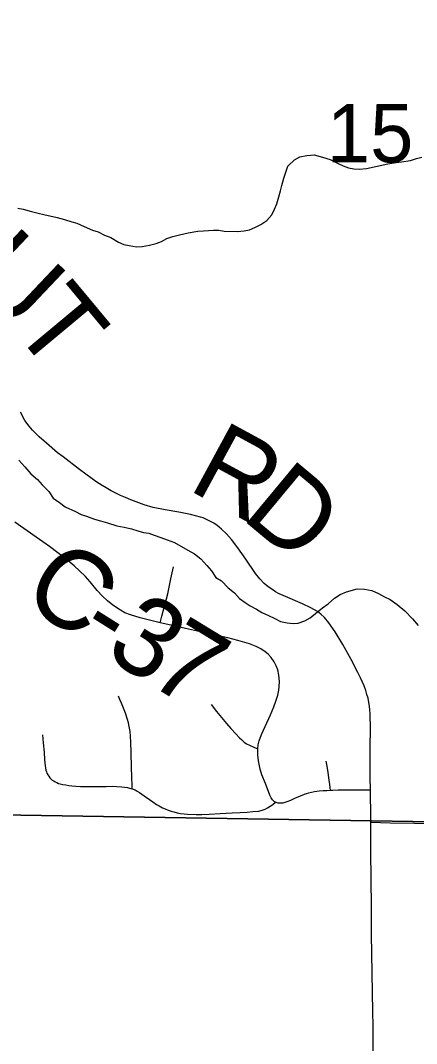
# Model space of a CAD drawing. Extents: x -8.8 to 41.4, y 0 to 34.6.
# Drawn here: x 2.586 to 2.87, y 15.426 to 16.161 of the extents above; entities that cross this region are included whole.
import ezdxf

# ---------------------------------------------------------------- set-up
doc = ezdxf.new("R2010")
doc.units = 0
for name, color, linetype in [('GM_X_Corporation', 7, 'Continuous'), ('GM_X_County_Road', 7, 'Continuous'), ('GM_X_Minor_River', 7, 'Continuous'), ('GM_X_Township_Road', 7, 'Continuous'), ('GM_X_Township_Road_Text', 7, 'Continuous'), ('GM_X_Township_Text', 7, 'Continuous')]:
    doc.layers.add(name, color=color, linetype=linetype)

msp = doc.modelspace()

# ---------------------------------------------------------------- linework, layer by layer
at = {"layer": 'GM_X_Corporation'}
for points in [[(2.35425, 16.60371), (3.32694, 16.59683), (3.3275, 15.57832), (2.34821, 15.59413)], [(2.34821, 15.59413), (3.3275, 15.57832), (3.32677, 14.56494), (2.34975, 14.59623)]]:
    msp.add_lwpolyline(points, close=True, dxfattribs=at)
at = {"layer": 'GM_X_County_Road'}
for points in [[(2.83763, 15.58529), (2.83742, 15.59449), (2.83723, 15.60243), (2.83721, 15.60834), (2.83716, 15.61761), (2.83712, 15.62667), (2.83714, 15.63601), (2.83725, 15.65583), (2.83716, 15.65981), (2.83696, 15.66326), (2.83679, 15.66619), (2.83652, 15.66869), (2.83605, 15.67147), (2.8355, 15.67452), (2.83476, 15.6772), (2.83383, 15.68007), (2.83263, 15.68322), (2.83142, 15.68599), (2.83003, 15.68905), (2.82818, 15.69299), (2.82339, 15.70232), (2.81735, 15.71309), (2.81182, 15.72202), (2.80722, 15.72856), (2.80414, 15.73233), (2.80152, 15.73485), (2.79915, 15.73667), (2.79442, 15.7394), (2.78827, 15.74223), (2.77457, 15.74818), (2.77172, 15.74947), (2.76895, 15.75098), (2.76623, 15.75267), (2.76368, 15.75449), (2.76073, 15.75687), (2.75758, 15.7602), (2.75458, 15.7641), (2.74756, 15.77443), (2.74191, 15.78254), (2.73743, 15.78841), (2.73377, 15.79255), (2.73024, 15.79592), (2.72843, 15.79743), (2.72693, 15.79859), (2.72452, 15.80016), (2.72228, 15.80149), (2.7203, 15.80246), (2.71844, 15.80328), (2.71688, 15.80395), (2.71504, 15.80463), (2.71142, 15.80556), (2.70792, 15.80646), (2.7031, 15.80737), (2.69944, 15.8081), (2.68962, 15.80972), (2.68104, 15.81147), (2.67441, 15.81337), (2.66504, 15.81694), (2.66098, 15.81868), (2.65759, 15.82019), (2.65404, 15.82183), (2.65086, 15.82349), (2.6472, 15.82551), (2.64436, 15.82726), (2.6404, 15.82977), (2.63707, 15.8321), (2.628, 15.83871), (2.61618, 15.84779), (2.61226, 15.85086), (2.60417, 15.85764), (2.599, 15.86216), (2.59408, 15.86696), (2.59169, 15.86989), (2.58875, 15.87394), (2.58551, 15.88004)], [(2.83924, 15.41958), (2.83909, 15.43879), (2.83895, 15.44935), (2.83806, 15.50465), (2.83791, 15.52579), (2.83783, 15.54318), (2.8375, 15.56555), (2.83763, 15.58529)]]:
    msp.add_lwpolyline(points, dxfattribs=at)
at = {"layer": 'GM_X_Minor_River'}
for points in [[(2.6561, 16.0022), (2.65984, 16.00055), (2.66361, 15.99965), (2.6689, 15.9987), (2.67309, 15.99893), (2.67844, 15.99988), (2.68305, 16.00124), (2.6869, 16.00262), (2.69078, 16.00476), (2.69501, 16.00613), (2.7, 16.00748), (2.70613, 16.00878), (2.71302, 16.01005), (2.71721, 16.01028), (2.72445, 16.01079), (2.72825, 16.01065), (2.73203, 16.01013), (2.74152, 16.00979), (2.74649, 16.01038), (2.75031, 16.011), (2.75417, 16.01277), (2.75843, 16.0149), (2.76272, 16.01778), (2.76628, 16.02184), (2.76833, 16.02595), (2.76999, 16.0297), (2.77131, 16.0346), (2.77261, 16.03911), (2.7735, 16.04288), (2.77484, 16.04816), (2.77653, 16.05305), (2.77781, 16.05681), (2.78253, 16.0612), (2.78641, 16.06335), (2.79138, 16.06431), (2.79673, 16.06488), (2.80274, 16.06314), (2.80838, 16.06142), (2.81398, 16.05855), (2.81773, 16.0569), (2.82148, 16.05562), (2.82525, 16.05473), (2.82943, 16.05458), (2.83439, 16.05516), (2.84971, 16.05842), (2.85583, 16.05934), (2.85965, 16.05996), (2.86615, 16.06087), (2.87038, 16.06224), (2.87421, 16.06324)], [(2.5836, 16.02648), (2.58739, 16.02596), (2.59341, 16.02423), (2.5983, 16.02291), (2.60245, 16.022), (2.61187, 16.01976), (2.61715, 16.01843), (2.62241, 16.01672), (2.62618, 16.01583), (2.63141, 16.01336), (2.6374, 16.01086), (2.64154, 16.00957), (2.64601, 16.00713), (2.65051, 16.00545), (2.6561, 16.0022)], [(2.58431, 15.84538), (2.5887, 15.84066), (2.59308, 15.83556), (2.59788, 15.83158), (2.60116, 15.82766), (2.60593, 15.82293), (2.60918, 15.81824), (2.61363, 15.81504), (2.61769, 15.81185), (2.62518, 15.80854), (2.62928, 15.80649), (2.63304, 15.80522), (2.63867, 15.80312), (2.64318, 15.80181), (2.64808, 15.80049), (2.65484, 15.79835), (2.66013, 15.7974), (2.6654, 15.79607), (2.66992, 15.79477), (2.67405, 15.79348), (2.67784, 15.79296), (2.68159, 15.79169), (2.68647, 15.78999), (2.69097, 15.78831), (2.69622, 15.78622), (2.70591, 15.78092), (2.71075, 15.77809), (2.71519, 15.77451), (2.71958, 15.76978), (2.72286, 15.76586), (2.72611, 15.76118), (2.7302, 15.75875), (2.73496, 15.75364), (2.73939, 15.75006), (2.74305, 15.74612), (2.74713, 15.74331), (2.75085, 15.7409), (2.75532, 15.73845), (2.75904, 15.73604), (2.7639, 15.73396), (2.76801, 15.73191)], [(2.76801, 15.73191), (2.77249, 15.72947), (2.77739, 15.72853), (2.78156, 15.728), (2.78537, 15.72825), (2.78999, 15.72998), (2.79387, 15.73213), (2.79779, 15.73541), (2.80287, 15.73941), (2.80678, 15.74231), (2.81149, 15.74633), (2.81538, 15.74885), (2.82002, 15.75097), (2.82769, 15.75298), (2.83301, 15.75279), (2.8383, 15.75184), (2.84316, 15.74976), (2.84726, 15.74733), (2.85136, 15.74528), (2.85656, 15.74167), (2.8621, 15.73729), (2.86759, 15.73139), (2.8716, 15.72668)]]:
    msp.add_lwpolyline(points, dxfattribs=at)
at = {"layer": 'GM_X_Township_Road'}
for points in [[(2.83721, 15.60834), (2.83541, 15.60833), (2.83031, 15.60836), (2.82391, 15.60835), (2.81755, 15.60835), (2.81392, 15.60825), (2.81008, 15.60814), (2.80862, 15.60807), (2.80589, 15.60797), (2.80321, 15.60781), (2.80036, 15.60753), (2.79699, 15.60713), (2.79479, 15.60678), (2.79265, 15.60628), (2.79104, 15.60581), (2.78958, 15.60532), (2.78661, 15.604), (2.7827, 15.60229), (2.77978, 15.601), (2.77705, 15.59994), (2.77566, 15.59949), (2.7742, 15.59913), (2.77343, 15.59903), (2.7725, 15.59893), (2.77169, 15.59893), (2.77082, 15.59903), (2.77012, 15.59915), (2.769, 15.59962), (2.76789, 15.60029), (2.76725, 15.60084), (2.76675, 15.60143), (2.76621, 15.60215), (2.76581, 15.60294), (2.765, 15.60487), (2.76174, 15.6132), (2.75917, 15.61946), (2.75787, 15.62349), (2.75666, 15.62947), (2.75618, 15.63368), (2.75622, 15.63816), (2.75655, 15.64086), (2.75726, 15.64375), (2.75899, 15.64831), (2.76544, 15.66244), (2.76769, 15.66827), (2.7693, 15.67231), (2.77064, 15.67652), (2.77141, 15.68023), (2.77171, 15.68273), (2.77177, 15.68653), (2.77136, 15.69098), (2.77054, 15.69474), (2.76946, 15.69778), (2.768, 15.70064), (2.76581, 15.7038), (2.76363, 15.7062), (2.76161, 15.70784), (2.75838, 15.7099), (2.75497, 15.71161), (2.75026, 15.71345), (2.74188, 15.71601), (2.73457, 15.71772), (2.72367, 15.72019), (2.70427, 15.7245), (2.68729, 15.72825), (2.68599, 15.72858), (2.67167, 15.73215), (2.66463, 15.73432), (2.66071, 15.7359), (2.65754, 15.73767), (2.65188, 15.74138), (2.64802, 15.74438), (2.64447, 15.74773), (2.64073, 15.75179), (2.63567, 15.75804), (2.63236, 15.76183), (2.62802, 15.76598), (2.62422, 15.76962), (2.61845, 15.77442), (2.60648, 15.78336), (2.59687, 15.79022), (2.5816, 15.80085)], [(2.68599, 15.72858), (2.68722, 15.73328), (2.69144, 15.74945), (2.69372, 15.76033), (2.69555, 15.76879)], [(2.66589, 15.60938), (2.66584, 15.61122), (2.66566, 15.61799), (2.66548, 15.62471), (2.6652, 15.63531), (2.665, 15.64295), (2.6647, 15.64715), (2.66433, 15.65042), (2.66379, 15.65416), (2.66325, 15.65673), (2.66258, 15.65905), (2.66111, 15.6638), (2.65976, 15.66734), (2.65824, 15.67085), (2.65708, 15.67355), (2.65603, 15.676)], [(2.72272, 15.66986), (2.72658, 15.66499), (2.73023, 15.66049), (2.73364, 15.65629), (2.73682, 15.65263), (2.74036, 15.64894), (2.74312, 15.64598), (2.74466, 15.64443), (2.74654, 15.6428), (2.74822, 15.6417), (2.75029, 15.64067), (2.75338, 15.63927), (2.75622, 15.63816)], [(2.60151, 15.64816), (2.60196, 15.64237), (2.60248, 15.63569), (2.60279, 15.63022), (2.60328, 15.62588), (2.60346, 15.62444), (2.60381, 15.62283), (2.6042, 15.62154), (2.60462, 15.62048), (2.60518, 15.61939), (2.60585, 15.61833), (2.60666, 15.61724), (2.60748, 15.61646), (2.60846, 15.6156), (2.60943, 15.61495), (2.61061, 15.61423), (2.6116, 15.61379), (2.61288, 15.61326), (2.61417, 15.61283), (2.61593, 15.61247), (2.61816, 15.61208), (2.62035, 15.61177), (2.62247, 15.61157), (2.62539, 15.6113), (2.62866, 15.6111), (2.63641, 15.61106), (2.64349, 15.61102), (2.64716, 15.61107), (2.65151, 15.61113), (2.65486, 15.61099), (2.65833, 15.61077), (2.66041, 15.61056), (2.66264, 15.61022), (2.66404, 15.6099), (2.66589, 15.60938), (2.66794, 15.60856), (2.66952, 15.60775), (2.67116, 15.60667), (2.67445, 15.60436), (2.67828, 15.60168), (2.68081, 15.59993), (2.6834, 15.59817), (2.68531, 15.59703), (2.68773, 15.59574), (2.6896, 15.59493), (2.69171, 15.59401), (2.69386, 15.59332), (2.69585, 15.5927), (2.69824, 15.59215), (2.7007, 15.5917), (2.70324, 15.59133), (2.70563, 15.59109), (2.71183, 15.59084), (2.7161, 15.59094), (2.72115, 15.5911), (2.72924, 15.59155), (2.73779, 15.59201), (2.74348, 15.59232), (2.74859, 15.59266), (2.75277, 15.59291), (2.75691, 15.59336), (2.75933, 15.59387), (2.76144, 15.59473), (2.76332, 15.59578), (2.76523, 15.59692), (2.76703, 15.59797), (2.769, 15.59962)], [(2.80862, 15.60807), (2.808, 15.61243), (2.80754, 15.61557), (2.80675, 15.62095), (2.80607, 15.62557), (2.80546, 15.62921)], [(2.83763, 15.58529), (2.8515, 15.58491), (2.86888, 15.58454), (2.87758, 15.58444)]]:
    msp.add_lwpolyline(points, dxfattribs=at)

# ---------------------------------------------------------------- texts
at = {"layer": 'GM_X_Township_Road_Text'}
for s, rotation, p in [('U', 316.5618, (2.54312, 15.9743)), ('T', 309.76908, (2.57821, 15.94122)), ('R', 331.49623, (2.70486, 15.82489)), ('D', 320.27827, (2.74344, 15.80426)), ('C', 326.1573, (2.58454, 15.74484)), ('3', 327.94821, (2.64468, 15.70537)), ('-', 327.83959, (2.62483, 15.71785)), ('7', 328.63749, (2.67498, 15.6864))]:
    msp.add_text(s, height=0.05682, rotation=rotation, dxfattribs=at).set_placement(p)
at = {"layer": 'GM_X_Township_Text'}
msp.add_text('15', height=0.041856, rotation=0.00001, dxfattribs=at).set_placement((2.80587, 16.05953))

doc.saveas('drawing.dxf')
